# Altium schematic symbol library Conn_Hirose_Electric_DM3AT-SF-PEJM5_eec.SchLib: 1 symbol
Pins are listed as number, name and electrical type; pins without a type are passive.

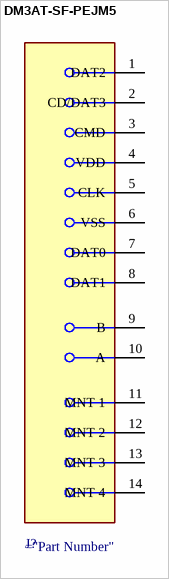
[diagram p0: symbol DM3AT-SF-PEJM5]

## DM3AT-SF-PEJM5
designator J?  (value not drawn)
pins: 1 DAT2, 2 CD/DAT3, 3 CMD, 4 VDD, 5 CLK, 6 VSS, 7 DAT0, 8 DAT1, 9 B, 10 A, 11 MNT 1, 12 MNT 2, 13 MNT 3, 14 MNT 4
